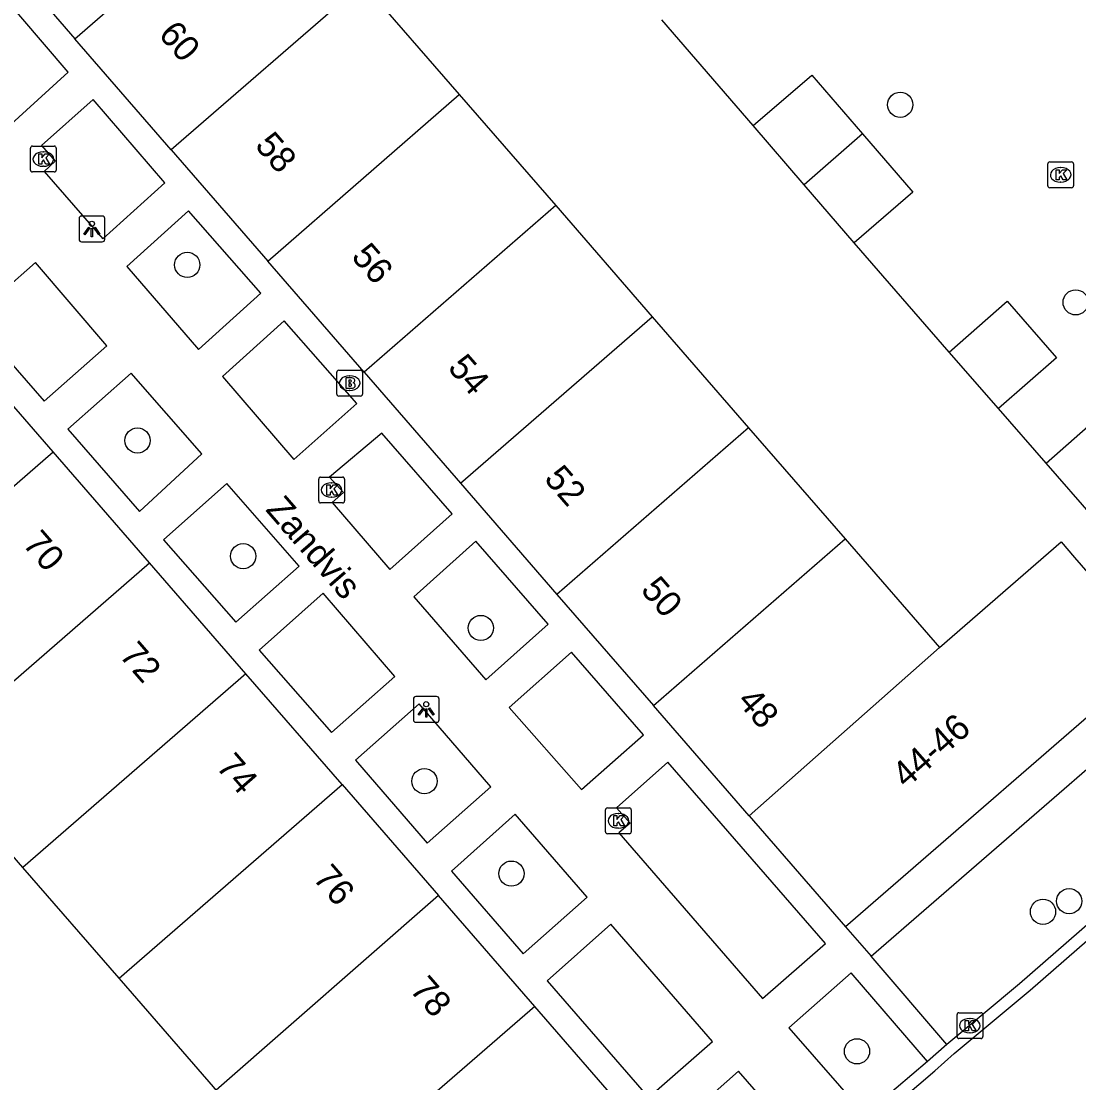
# Model space of a CAD drawing. Extents: x 155888 to 156864, y 383882 to 384671.
# Drawn here: x 156611.38 to 156652.41, y 384332.55 to 384373.73 of the extents above; entities that cross this region are included whole.
import ezdxf

# ---------------------------------------------------------------- set-up
doc = ezdxf.new("R2010")
doc.units = 0
for name, color, linetype in [('IMGEO_Boom', 7, 'Continuous'), ('IMGEO_Brandkraan', 7, 'Continuous'), ('IMGEO_Kolk', 7, 'Continuous'), ('IMGEO_Lichtpunt', 7, 'Continuous'), ('IMGEO_Openbare_ruimte_label', 7, 'Continuous'), ('IMGEO_Pand', 7, 'Continuous'), ('IMGEO_Pand_nummerreeks', 7, 'Continuous'), ('IMGEO_Rijbaan_lokaal_gesloten', 7, 'Continuous'), ('IMGEO_Rijbaan_lokaal_open', 7, 'Continuous'), ('IMGEO_Voetpad_open', 7, 'Continuous')]:
    doc.layers.add(name, color=color, linetype=linetype)

msp = doc.modelspace()

# ---------------------------------------------------------------- linework, layer by layer
at = {"layer": 'IMGEO_Boom'}
for centre in [(156645.481, 384370.488), (156617.822, 384364.275), (156652.287, 384362.821), (156615.891, 384357.463), (156619.991, 384352.977), (156629.209, 384350.19), (156627.023, 384344.247), (156630.398, 384340.661), (156652.035, 384339.593), (156651.019, 384339.181), (156643.804, 384333.767)]:
    msp.add_circle(centre, 0.489, dxfattribs=at)
at = {"layer": 'IMGEO_Brandkraan'}
for p, q in [((156623.621, 384359.262), (156623.621, 384360.114)), ((156623.696, 384360.188), (156624.548, 384360.188)), ((156624.109, 384359.968), (156624.134, 384359.968)), ((156624.622, 384360.114), (156624.622, 384359.262)), ((156624.548, 384359.188), (156623.696, 384359.188)), ((156624.132, 384359.408), (156624.107, 384359.408))]:
    msp.add_line(p, q, dxfattribs=at)
for points in [[(156623.621, 384359.262), (156623.621, 384360.114)], [(156623.696, 384360.188), (156624.548, 384360.188)], [(156624.622, 384360.114), (156624.622, 384359.262)], [(156623.969, 384359.888), (156623.969, 384359.488), (156624.182, 384359.488)], [(156624.2, 384359.888), (156623.969, 384359.888)], [(156624.148, 384359.807), (156624.094, 384359.807), (156624.094, 384359.731)], [(156624.094, 384359.731), (156624.147, 384359.731)], [(156624.156, 384359.655), (156624.094, 384359.655), (156624.094, 384359.574)], [(156624.094, 384359.574), (156624.156, 384359.574)], [(156624.548, 384359.188), (156623.696, 384359.188)]]:
    msp.add_lwpolyline(points, dxfattribs=at)
for centre, radius, start, end in [((156623.698, 384360.112), 0.0765, 91.552, 178.448), ((156623.698, 384360.112), 0.0765, 91.552, 178.448), ((156624.546, 384360.112), 0.0765, 1.552, 88.448), ((156624.546, 384360.112), 0.0765, 1.552, 88.448), ((156624.149, 384359.769), 0.0379, 267.8285, 90.9355), ((156624.157, 384359.614), 0.0404, 269.8759, 90.5077), ((156624.204, 384359.743), 0.145, 59.4692, 91.5367), ((156624.229, 384359.79), 0.0922, 285.5137, 58.1501), ((156624.234, 384359.598), 0.105, 301.3115, 78.989), ((156623.698, 384359.264), 0.0765, 181.552, 268.448), ((156623.698, 384359.264), 0.0765, 181.552, 268.448), ((156624.188, 384359.739), 0.251, 268.6676, 293.5347), ((156624.546, 384359.264), 0.0765, 271.552, 358.448), ((156624.546, 384359.264), 0.0765, 271.552, 358.448)]:
    msp.add_arc(centre, radius, start, end, dxfattribs=at)
for centre, major_axis, ratio, start_param, end_param in [((156624.108, 384359.688), (-0.387, 0.002), 0.722429, 4.712389, 7.853982), ((156624.133, 384359.688), (-0.39, 0.002), 0.717154, 1.570796, 4.712389)]:
    msp.add_ellipse(centre, major_axis=major_axis, ratio=ratio, start_param=start_param, end_param=end_param, dxfattribs=at)
at = {"layer": 'IMGEO_Kolk'}
for p, q in [((156611.737, 384367.955), (156611.737, 384368.807)), ((156611.812, 384368.881), (156612.664, 384368.881)), ((156612.225, 384368.661), (156612.25, 384368.661)), ((156612.738, 384368.807), (156612.738, 384367.955)), ((156651.204, 384367.343), (156651.204, 384368.195)), ((156651.279, 384368.269), (156652.131, 384368.269)), ((156652.205, 384368.195), (156652.205, 384367.343)), ((156612.664, 384367.881), (156611.812, 384367.881)), ((156612.248, 384368.101), (156612.223, 384368.101)), ((156651.692, 384368.049), (156651.717, 384368.049)), ((156651.715, 384367.489), (156651.69, 384367.489)), ((156652.131, 384367.269), (156651.279, 384367.269)), ((156622.921, 384355.116), (156622.921, 384355.968)), ((156622.996, 384356.042), (156623.848, 384356.042)), ((156623.922, 384355.968), (156623.922, 384355.116)), ((156623.409, 384355.822), (156623.434, 384355.822)), ((156623.848, 384355.042), (156622.996, 384355.042)), ((156623.432, 384355.262), (156623.407, 384355.262)), ((156634.045, 384342.284), (156634.045, 384343.136)), ((156634.12, 384343.21), (156634.972, 384343.21)), ((156635.046, 384343.136), (156635.046, 384342.284)), ((156634.533, 384342.99), (156634.558, 384342.99)), ((156634.556, 384342.43), (156634.531, 384342.43)), ((156634.972, 384342.21), (156634.12, 384342.21)), ((156647.76, 384335.263), (156648.612, 384335.263)), ((156647.685, 384334.337), (156647.685, 384335.189)), ((156648.173, 384335.043), (156648.198, 384335.043)), ((156648.686, 384335.189), (156648.686, 384334.337)), ((156648.196, 384334.483), (156648.171, 384334.483)), ((156648.612, 384334.263), (156647.76, 384334.263))]:
    msp.add_line(p, q, dxfattribs=at)
for points in [[(156611.737, 384367.955), (156611.737, 384368.807)], [(156611.812, 384368.881), (156612.664, 384368.881)], [(156612.738, 384368.807), (156612.738, 384367.955)], [(156612.058, 384368.581), (156612.181, 384368.581), (156612.181, 384368.43), (156612.311, 384368.581), (156612.475, 384368.581), (156612.329, 384368.43), (156612.482, 384368.181), (156612.33, 384368.181), (156612.245, 384368.345), (156612.181, 384368.278), (156612.181, 384368.181), (156612.058, 384368.181), (156612.058, 384368.581)], [(156651.204, 384367.343), (156651.204, 384368.195)], [(156651.279, 384368.269), (156652.131, 384368.269)], [(156652.205, 384368.195), (156652.205, 384367.343)], [(156612.664, 384367.881), (156611.812, 384367.881)], [(156651.525, 384367.969), (156651.648, 384367.969), (156651.648, 384367.818), (156651.778, 384367.969), (156651.942, 384367.969), (156651.796, 384367.818), (156651.949, 384367.569), (156651.797, 384367.569), (156651.712, 384367.733), (156651.648, 384367.666), (156651.648, 384367.569), (156651.525, 384367.569), (156651.525, 384367.969)], [(156652.131, 384367.269), (156651.279, 384367.269)], [(156622.921, 384355.116), (156622.921, 384355.968)], [(156622.996, 384356.042), (156623.848, 384356.042)], [(156623.922, 384355.968), (156623.922, 384355.116)], [(156623.242, 384355.742), (156623.365, 384355.742), (156623.365, 384355.591), (156623.495, 384355.742), (156623.659, 384355.742), (156623.513, 384355.591), (156623.666, 384355.342), (156623.514, 384355.342), (156623.429, 384355.506), (156623.365, 384355.439), (156623.365, 384355.342), (156623.242, 384355.342), (156623.242, 384355.742)], [(156623.848, 384355.042), (156622.996, 384355.042)], [(156634.045, 384342.284), (156634.045, 384343.136)], [(156634.12, 384343.21), (156634.972, 384343.21)], [(156635.046, 384343.136), (156635.046, 384342.284)], [(156634.366, 384342.91), (156634.489, 384342.91), (156634.489, 384342.759), (156634.619, 384342.91), (156634.783, 384342.91), (156634.637, 384342.759), (156634.79, 384342.51), (156634.638, 384342.51), (156634.553, 384342.674), (156634.489, 384342.607), (156634.489, 384342.51), (156634.366, 384342.51), (156634.366, 384342.91)], [(156634.972, 384342.21), (156634.12, 384342.21)], [(156647.76, 384335.263), (156648.612, 384335.263)], [(156647.685, 384334.337), (156647.685, 384335.189)], [(156648.006, 384334.963), (156648.129, 384334.963), (156648.129, 384334.812), (156648.259, 384334.963), (156648.423, 384334.963), (156648.277, 384334.812), (156648.43, 384334.563), (156648.278, 384334.563), (156648.193, 384334.727), (156648.129, 384334.66), (156648.129, 384334.563), (156648.006, 384334.563), (156648.006, 384334.963)], [(156648.686, 384335.189), (156648.686, 384334.337)], [(156648.612, 384334.263), (156647.76, 384334.263)]]:
    msp.add_lwpolyline(points, dxfattribs=at)
for centre, start, end in [((156611.814, 384368.805), 91.552, 178.448), ((156611.814, 384368.805), 91.552, 178.448), ((156612.662, 384368.805), 1.552, 88.448), ((156612.662, 384368.805), 1.552, 88.448), ((156651.281, 384368.193), 91.552, 178.448), ((156651.281, 384368.193), 91.552, 178.448), ((156652.129, 384368.193), 1.552, 88.448), ((156652.129, 384368.193), 1.552, 88.448), ((156611.814, 384367.957), 181.552, 268.448), ((156611.814, 384367.957), 181.552, 268.448), ((156612.662, 384367.957), 271.552, 358.448), ((156612.662, 384367.957), 271.552, 358.448), ((156651.281, 384367.345), 181.552, 268.448), ((156651.281, 384367.345), 181.552, 268.448), ((156652.129, 384367.345), 271.552, 358.448), ((156652.129, 384367.345), 271.552, 358.448), ((156622.998, 384355.966), 91.552, 178.448), ((156622.998, 384355.966), 91.552, 178.448), ((156623.846, 384355.966), 1.552, 88.448), ((156623.846, 384355.966), 1.552, 88.448), ((156622.998, 384355.118), 181.552, 268.448), ((156622.998, 384355.118), 181.552, 268.448), ((156623.846, 384355.118), 271.552, 358.448), ((156623.846, 384355.118), 271.552, 358.448), ((156634.122, 384343.134), 91.552, 178.448), ((156634.122, 384343.134), 91.552, 178.448), ((156634.97, 384343.134), 1.552, 88.448), ((156634.97, 384343.134), 1.552, 88.448), ((156634.122, 384342.286), 181.552, 268.448), ((156634.122, 384342.286), 181.552, 268.448), ((156634.97, 384342.286), 271.552, 358.448), ((156634.97, 384342.286), 271.552, 358.448), ((156647.762, 384335.187), 91.552, 178.448), ((156647.762, 384335.187), 91.552, 178.448), ((156648.61, 384335.187), 1.552, 88.448), ((156648.61, 384335.187), 1.552, 88.448), ((156647.762, 384334.339), 181.552, 268.448), ((156647.762, 384334.339), 181.552, 268.448), ((156648.61, 384334.339), 271.552, 358.448), ((156648.61, 384334.339), 271.552, 358.448)]:
    msp.add_arc(centre, 0.0765, start, end, dxfattribs=at)
for centre, major_axis, ratio, start_param, end_param in [((156612.224, 384368.381), (-0.387, 0.002), 0.722429, 4.712389, 7.853982), ((156612.249, 384368.381), (-0.39, 0.002), 0.717154, 1.570796, 4.712389), ((156651.691, 384367.769), (-0.387, 0.002), 0.722429, 4.712389, 7.853982), ((156651.716, 384367.769), (-0.39, 0.002), 0.717154, 1.570796, 4.712389), ((156623.408, 384355.542), (-0.387, 0.002), 0.722429, 4.712389, 7.853982), ((156623.433, 384355.542), (-0.39, 0.002), 0.717154, 1.570796, 4.712389), ((156634.532, 384342.71), (-0.387, 0.002), 0.722429, 4.712389, 7.853982), ((156634.557, 384342.71), (-0.39, 0.002), 0.717154, 1.570796, 4.712389), ((156648.172, 384334.763), (-0.387, 0.002), 0.722429, 4.712389, 7.853982), ((156648.197, 384334.763), (-0.39, 0.002), 0.717154, 1.570796, 4.712389)]:
    msp.add_ellipse(centre, major_axis=major_axis, ratio=ratio, start_param=start_param, end_param=end_param, dxfattribs=at)
at = {"layer": 'IMGEO_Lichtpunt'}
for p, q in [((156614.526, 384366.167), (156613.718, 384366.167)), ((156614.526, 384366.167), (156613.718, 384366.167)), ((156613.624, 384366.072), (156613.624, 384365.265)), ((156613.624, 384366.072), (156613.624, 384365.265)), ((156614.62, 384365.265), (156614.62, 384366.072)), ((156614.62, 384365.265), (156614.62, 384366.072)), ((156613.718, 384365.171), (156614.526, 384365.171)), ((156613.718, 384365.171), (156614.526, 384365.171)), ((156626.595, 384347.434), (156626.595, 384346.627)), ((156626.595, 384347.434), (156626.595, 384346.627)), ((156627.497, 384347.529), (156626.689, 384347.529)), ((156627.497, 384347.529), (156626.689, 384347.529)), ((156627.591, 384346.627), (156627.591, 384347.434)), ((156627.591, 384346.627), (156627.591, 384347.434)), ((156626.689, 384346.533), (156627.497, 384346.533)), ((156626.689, 384346.533), (156627.497, 384346.533))]:
    msp.add_line(p, q, dxfattribs=at)
for points in [[(156613.998, 384365.736), (156614.037, 384365.708), (156613.849, 384365.446), (156613.811, 384365.473), (156613.998, 384365.736)], [(156614.21, 384365.708), (156614.248, 384365.735), (156614.435, 384365.473), (156614.396, 384365.445), (156614.21, 384365.708)], [(156614.1, 384365.688), (156614.147, 384365.688), (156614.147, 384365.366), (156614.1, 384365.366), (156614.1, 384365.688)], [(156626.969, 384347.098), (156627.008, 384347.07), (156626.82, 384346.808), (156626.782, 384346.835), (156626.969, 384347.098)], [(156627.071, 384347.05), (156627.118, 384347.05), (156627.118, 384346.728), (156627.071, 384346.728), (156627.071, 384347.05)], [(156627.181, 384347.07), (156627.219, 384347.097), (156627.406, 384346.835), (156627.367, 384346.807), (156627.181, 384347.07)]]:
    msp.add_lwpolyline(points, dxfattribs=at)
for centre in [(156614.123, 384365.87), (156627.094, 384347.232)]:
    msp.add_circle(centre, 0.0994, dxfattribs=at)
for centre, start, end in [((156613.718, 384366.072), 90, 180), ((156613.718, 384366.072), 90, 180), ((156614.526, 384366.072), 0, 90), ((156614.526, 384366.072), 0, 90), ((156613.718, 384365.265), 180, 270), ((156613.718, 384365.265), 180, 270), ((156614.526, 384365.265), 270, 0), ((156614.526, 384365.265), 270, 360), ((156626.689, 384347.434), 90, 180), ((156626.689, 384347.434), 90, 180), ((156627.497, 384347.434), 0, 90), ((156627.497, 384347.434), 0, 90), ((156626.689, 384346.627), 180, 270), ((156626.689, 384346.627), 180, 270), ((156627.497, 384346.627), 270, 0), ((156627.497, 384346.627), 270, 360)]:
    msp.add_arc(centre, 0.0946, start, end, dxfattribs=at)
at = {"layer": 'IMGEO_Pand'}
for points in [[(156613.458, 384373.047), (156620.894, 384379.505)], [(156609.692, 384377.385), (156613.458, 384373.047)], [(156624.635, 384375.195), (156617.2, 384368.735)], [(156624.635, 384375.195), (156628.376, 384370.886)], [(156617.2, 384368.735), (156613.458, 384373.047)], [(156639.775, 384369.677), (156642.045, 384371.638), (156644.018, 384369.355)], [(156620.941, 384364.426), (156628.376, 384370.886)], [(156628.376, 384370.886), (156632.118, 384366.575)], [(156641.753, 384367.387), (156639.775, 384369.677)], [(156644.018, 384369.355), (156641.753, 384367.387)], [(156644.018, 384369.355), (156645.968, 384367.097), (156643.698, 384365.136)], [(156617.2, 384368.735), (156620.941, 384364.426)], [(156643.698, 384365.136), (156641.753, 384367.387)], [(156632.118, 384366.575), (156624.683, 384360.115)], [(156632.118, 384366.575), (156635.858, 384362.266)], [(156624.683, 384360.115), (156620.941, 384364.426)], [(156647.373, 384360.895), (156649.632, 384362.869), (156651.548, 384360.676), (156649.289, 384358.702)], [(156628.423, 384355.807), (156635.858, 384362.266)], [(156635.858, 384362.266), (156639.6, 384357.955)], [(156612.624, 384357.019), (156608.888, 384361.32)], [(156649.289, 384358.702), (156647.373, 384360.895)], [(156624.683, 384360.115), (156628.423, 384355.807)], [(156651.143, 384356.581), (156655.162, 384360.131), (156657.005, 384358.01)], [(156639.6, 384357.955), (156632.165, 384351.495)], [(156639.6, 384357.955), (156643.339, 384353.647)], [(156657.005, 384358.01), (156652.986, 384354.46), (156651.143, 384356.581)], [(156605.639, 384350.953), (156612.624, 384357.019)], [(156616.359, 384352.718), (156612.624, 384357.019)], [(156628.423, 384355.807), (156632.165, 384351.495)], [(156635.904, 384347.188), (156643.339, 384353.647)], [(156643.339, 384353.647), (156646.998, 384349.432)], [(156646.998, 384349.432), (156651.72, 384353.528), (156652.245, 384352.924), (156655.521, 384349.147)], [(156609.374, 384346.652), (156616.359, 384352.718)], [(156620.096, 384348.417), (156616.359, 384352.718)], [(156632.165, 384351.495), (156635.904, 384347.188)], [(156646.998, 384349.432), (156639.624, 384342.903)], [(156655.521, 384349.147), (156643.361, 384338.598)], [(156620.096, 384348.417), (156611.443, 384340.903)], [(156623.832, 384344.115), (156620.096, 384348.417)], [(156639.624, 384342.903), (156635.904, 384347.188)], [(156611.443, 384340.903), (156607.707, 384345.204), (156609.374, 384346.652)], [(156615.176, 384336.605), (156623.832, 384344.115)], [(156623.832, 384344.115), (156627.568, 384339.815)], [(156639.624, 384342.903), (156643.361, 384338.598)], [(156615.176, 384336.605), (156611.443, 384340.903)], [(156627.568, 384339.815), (156618.948, 384332.262)], [(156631.31, 384335.506), (156627.568, 384339.815)], [(156618.948, 384332.262), (156618.839, 384332.387), (156615.272, 384336.495), (156615.176, 384336.605)], [(156631.31, 384335.506), (156622.649, 384328.001)], [(156634.968, 384331.295), (156631.31, 384335.506)]]:
    msp.add_lwpolyline(points, dxfattribs=at)
at = {"layer": 'IMGEO_Rijbaan_lokaal_gesloten'}
msp.add_lwpolyline([(156644.425, 384330.963), (156646.82, 384333.008), (156647.579, 384333.681), (156650.518, 384336.137), (156665.515, 384349.203), (156668.2, 384351.564), (156677.151, 384359.329), (156686.013, 384367.047), (156686.835, 384367.746), (156689.151, 384369.782), (156691.155, 384371.506), (156693.59, 384373.623)], dxfattribs=at)
at = {"layer": 'IMGEO_Rijbaan_lokaal_open'}
for points in [[(156639.775, 384369.677), (156636.232, 384373.777)], [(156647.373, 384360.895), (156643.698, 384365.136)], [(156651.143, 384356.581), (156649.289, 384358.702)], [(156665.212, 384349.549), (156650.107, 384336.388), (156647.287, 384334.037)], [(156647.287, 384334.037), (156646.542, 384333.376)], [(156646.542, 384333.376), (156644.11, 384331.3)]]:
    msp.add_lwpolyline(points, dxfattribs=at)
at = {"layer": 'IMGEO_Voetpad_open'}
for points in [[(156610.435, 384374.979), (156608.025, 384372.827), (156610.845, 384369.603), (156613.198, 384371.753), (156610.435, 384374.979)], [(156616.958, 384367.454), (156614.166, 384370.687), (156612.168, 384368.913), (156612.694, 384368.295), (156612.274, 384367.904), (156614.542, 384365.287), (156616.958, 384367.454)], [(156617.864, 384366.375), (156615.476, 384364.219), (156618.256, 384360.993), (156620.682, 384363.177), (156617.864, 384366.375)], [(156611.932, 384364.364), (156609.469, 384362.191), (156612.275, 384358.983), (156614.702, 384361.134), (156611.932, 384364.364)], [(156621.583, 384362.103), (156619.184, 384359.94), (156621.96, 384356.722), (156624.401, 384358.895), (156621.583, 384362.103)], [(156615.648, 384360.08), (156613.193, 384357.903), (156615.972, 384354.71), (156618.387, 384356.944), (156615.648, 384360.08)], [(156625.373, 384357.752), (156623.338, 384356.041), (156623.884, 384355.443), (156623.443, 384355.062), (156625.683, 384352.454), (156628.097, 384354.623), (156625.373, 384357.752)], [(156619.354, 384355.794), (156616.905, 384353.614), (156619.709, 384350.415), (156622.164, 384352.593), (156619.354, 384355.794)], [(156629.016, 384353.553), (156626.608, 384351.4), (156629.4, 384348.177), (156631.82, 384350.334), (156629.016, 384353.553)], [(156644.351, 384337.46), (156662.255, 384352.978)], [(156623.088, 384351.534), (156620.614, 384349.328), (156623.413, 384346.139), (156625.872, 384348.309), (156623.088, 384351.534)], [(156632.729, 384349.257), (156630.31, 384347.11), (156633.116, 384343.925), (156635.526, 384346.048), (156632.729, 384349.257)], [(156626.818, 384347.244), (156624.344, 384345.058), (156627.134, 384341.84), (156629.598, 384344.022), (156626.818, 384347.244)], [(156636.465, 384344.979), (156634.473, 384343.209), (156635.01, 384342.614), (156634.566, 384342.241), (156640.143, 384335.819), (156642.587, 384337.954), (156636.465, 384344.979)], [(156630.544, 384342.968), (156628.067, 384340.762), (156630.849, 384337.546), (156633.334, 384339.753), (156630.544, 384342.968)], [(156634.257, 384338.695), (156631.78, 384336.499), (156635.712, 384331.974), (156638.198, 384334.154), (156634.257, 384338.695)], [(156643.361, 384338.598), (156644.351, 384337.46)], [(156647.287, 384334.037), (156644.351, 384337.46)], [(156646.542, 384333.376), (156643.583, 384336.813), (156641.158, 384334.679), (156644.11, 384331.3)], [(156642.167, 384329.593), (156639.21, 384332.992), (156636.72, 384330.797), (156639.639, 384327.386)]]:
    msp.add_lwpolyline(points, dxfattribs=at)

# ---------------------------------------------------------------- texts
at = {"layer": 'IMGEO_Openbare_ruimte_label'}
msp.add_text('Zandvis', height=1, rotation=310.9057, dxfattribs=at).set_placement((156620.828, 384354.764))
at = {"layer": 'IMGEO_Pand_nummerreeks'}
for s, rotation, p in [('60', 310.9596, (156616.668, 384373.194)), ('58', 310.9596, (156620.41, 384368.884)), ('56', 310.9596, (156624.149, 384364.575)), ('54', 310.9596, (156627.891, 384360.265)), ('52', 310.9596, (156631.63, 384355.957)), ('70', 310.9777, (156611.399, 384353.427)), ('50', 310.9596, (156635.376, 384351.643)), ('72', 310.9777, (156615.15, 384349.109)), ('48', 310.9596, (156639.117, 384347.333)), ('44-46', 41.2643, (156645.709, 384343.938)), ('74', 310.9784, (156618.907, 384344.785)), ('76', 310.9784, (156622.661, 384340.463)), ('78', 310.9777, (156626.418, 384336.137))]:
    msp.add_text(s, height=1, rotation=rotation, dxfattribs=at).set_placement(p)

doc.saveas('drawing.dxf')
